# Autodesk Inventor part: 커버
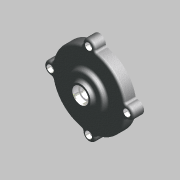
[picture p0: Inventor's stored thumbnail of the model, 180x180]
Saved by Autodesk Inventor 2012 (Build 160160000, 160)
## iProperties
Company: 한국ATC센터
Created: 2014-07
Part Number: 커버
Document SubType Name: 모델링
Designer: KYOUNG IL JANG
Material: 알루미늄-6061
Mass: 196.659 g
Surface Area: 278.607 cm^2
Volume: 72.5678 cm^3
Density: 2.71 g/cm^3
변환 표준: STEP AP214IS
파일 이름: C:\Users\SeoGD\Desktop\?쒗뿕\而ㅻ쾭-1.stp
전처리기: Build: 253, Release: 2010 SP1 - Date: Wed 07/29/2009
전송 단위: 밀리미터
불확실성: 0.01
Author: KYOUNG IL JANG
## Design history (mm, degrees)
sketch "스케치1"
  geometry: L1 (0, 0)-(0, 26); L2 (50, 0)-(50, 15); L3 (50, 15)-(25, 15); L4 (25, 15)-(25, 21); L5 (25, 21)-(15, 21); L6 (15, 21)-(13.66, 26); L7 (13.66, 26)-(10, 26); L8 (50, 0)-(45, 0); L9 (45, 0)-(45, 10); L10 (45, 10)-(14.5, 10); L11 (14.5, 10)-(13.266, 3); L12 (13.266, 3)-(11, 3); L13 (11, 3)-(11, 16); L14 (11, 16)-(7.5, 16); L15 (7.5, 16)-(7.5, 19); L16 (7.5, 19)-(10, 19); L17 (10, 19)-(10, 26)
  constraints: 34 end point, 10 parallel, 2 perpendicular, 2 point on line, 1 vertical
  dimensions: "d11" = 100 diameter of L2 L1; "d12" = 22 diameter of L13 L1; "d13" = 90 diameter of L9 L1; "d14" = 15 distance between parallel lines of L3 L8; "d15" = 10 distance between parallel lines of L8 L10; "d16" = 29 diameter of L10.end L1; "d17" = 100 deg angle of L11 L10; "d18" = 7 distance between parallel lines of L12 L10; "d19" = 13 distance between parallel lines of L14 L12; "d20" = 3 distance between parallel lines of L16 L14; "d21" = 15 diameter of L15 L1; "d22" = 20 diameter of L17 L1; "d23" = 30 diameter of L5.end L1; "d24" = 6 distance between parallel lines of L5 L3; "d25" = 50 diameter of L4 L1; "d26" = 105 deg angle of L5 L6; "d50" = 26 distance of L1.start L1.end
revolve "회전1" sketch "스케치1" stored, may be unused: angle "d27" = 90 deg
sketch "스케치2" dims "d29" = 104
  geometry: A1 r 8.5 centre (0, 52) between (8.074, 49.344) and (-8.074, 49.344); A2 r 50 centre (0, 0) between (-8.074, 49.344) and (8.074, 49.344) reference; 2 further points
  constraints: 4 point on circle, 2 vertical alignment, 1 centre point, 1 coincident, 2 other
  dimensions: "d28" = 17 diameter of A1
extrude "돌출1" join sketch "스케치2" stored distance "d30" = 10; taper "d31" = 0 deg
fillet "모깎기3" dims "d32" = 3
fillet "모깎기4" dims "d45" = 3, "d46" = 0.2
chamfer "모따기1" distance "d47" = 1; stored, may be unused: second distance "d48" = 2, angle "d49" = 45 deg
hole "구멍2" diameter "d38" = 5.5; stored, may be unused: countersink angle "d42" = 90 deg, drill point angle "d44" = 118 deg; dims "d36" = 10, "d37" = 10, "d39" = 6, "d40" = 9.5, "d41" = 5.4, "d43" = 8
node "솔리드1"
node "솔리드 본체"
node "곡면 본체"
pattern_circular "원형 패턴1" dims angle "d34" = 360 deg
pattern_circular "원형 패턴2" dims angle "d52" = 360 deg
node "솔리드2"
